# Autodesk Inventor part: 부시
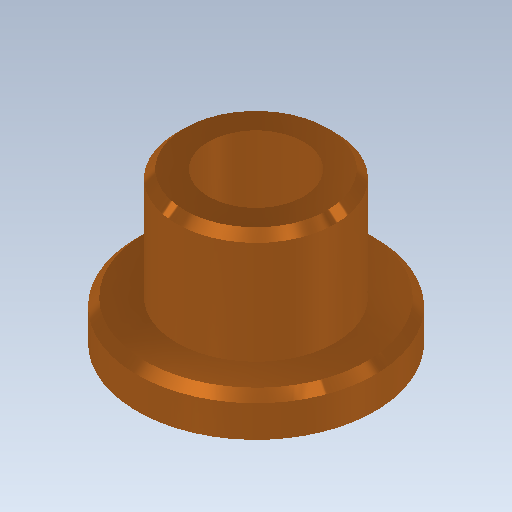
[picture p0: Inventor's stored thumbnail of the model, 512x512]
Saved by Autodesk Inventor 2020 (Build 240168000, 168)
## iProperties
Created: 2016-02
Part Number: 부시
Material: 스테인리스강
Document SubType Name: Modeling
Designer: mduedu
Density: 8.08 g/cm^3
Appearance: 금속 1600F 열
Author: mduedu
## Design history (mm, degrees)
sketch "스케치1"
  geometry: C1 r 15 at (0, 0); 1 further point
  constraints: 1 centre point, 1 coincident
  dimensions: "d0" = 30 diameter of C1
extrude "돌출1" new body sketch "스케치1" distance "d1" = 5; taper "d2" = 0 deg
sketch "스케치2"
  geometry: C1 r 10 at (0, 0); 1 further point
  constraints: 1 centre point, 1 coincident
  dimensions: "d3" = 20 diameter of C1
extrude "돌출2" join sketch "스케치2" distance "d4" = 14; taper "d5" = 0 deg
hole "구멍1" diameter "d8" = 12; stored, may be unused: countersink angle "d12" = 90 deg, drill point angle "d14" = 118 deg; dims "d9" = 6, "d10" = 4, "d11" = 2, "d13" = 8, "d15" = 10, "d16" = 10
chamfer "모따기1" distance "d17" = 1; stored, may be unused: second distance "d18" = 2, angle "d19" = 45 deg
chamfer "모따기2" distance "d20" = 1; stored, may be unused: second distance "d21" = 2, angle "d22" = 45 deg
chamfer "모따기3" distance "d23" = 1; stored, may be unused: second distance "d24" = 2, angle "d25" = 45 deg
node "솔리드1"
